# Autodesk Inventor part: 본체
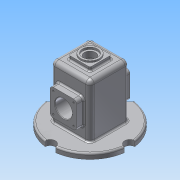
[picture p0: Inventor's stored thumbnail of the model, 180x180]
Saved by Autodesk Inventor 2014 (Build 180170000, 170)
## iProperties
Created: 2018-07
Part Number: 본체
Material: 알루미늄 6061
Document SubType Name: Modeling
Designer: user
Density: 2.71 g/cm^3
Appearance: 알루미늄 - 평지
Mass: 924.652 g
Surface Area: 1023.59 cm^2
Volume: 341.2 cm^3
Author: user
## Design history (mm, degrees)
sketch "스케치1"
  geometry: A1 r 10 centre (0, 75) between (9.978, 74.333) and (-9.978, 74.333); A2 r 10 centre (75, 0) between (74.333, -9.978) and (74.333, 9.978); A3 r 10 centre (0, -75) between (-9.978, -74.333) and (9.978, -74.333); A4 r 10 centre (-75, 0) between (-74.333, 9.978) and (-74.333, -9.978); A5 r 75 centre (0, 0) between (74.333, 9.978) and (9.978, 74.333); A6 r 75 centre (0, 0) between (9.978, -74.333) and (74.333, -9.978); A7 r 75 centre (0, 0) between (-9.978, 74.333) and (-74.333, 9.978); A8 r 75 centre (0, 0) between (-74.333, -9.978) and (-9.978, -74.333); 1 further point
  constraints: 16 point on circle, 8 centre point, 3 equal radius, 2 horizontal alignment, 2 vertical alignment, 1 coincident
  dimensions: "d5" = 75 radius of A5; "d6" = 75 radius of A6; "d7" = 75 radius of A8; "d8" = 75 radius of A7; "d9" = 150 distance of A4.centre A2.centre; "d10" = 150 distance of A3.centre A1.centre; "d11" = 75 distance of A1.centre point (0, 0); "d12" = 75 distance of point (0, 0) A2.centre; "d90" = 20 diameter of A3
extrude "돌출1" new body sketch "스케치1" distance "d13" = 10; taper "d14" = 0 deg
sketch "스케치2"
  geometry: L1 (-37, 37)-(37, 37); L2 (37, 37)-(37, -37); L3 (37, -37)-(-37, -37); L4 (-37, -37)-(-37, 37); L5 (-37, 37)-(37, -37); L6 (37, 37)-(-37, -37); A1 r 75 centre (0, 0) between (74.333, 9.978) and (9.978, 74.333) reference
  constraints: 12 end point, 2 midpoint, 2 parallel, 1 horizontal, 1 perpendicular
  dimensions: "d15" = 74 distance of L2.end L3.end; "d16" = 74 distance of L1.end L2.end
extrude "돌출2" join sketch "스케치2" distance "d17" = 100; taper "d18" = 0 deg
sketch "스케치3"
  geometry: L1 (-20, 20)-(20, 20); L2 (20, 20)-(20, -20); L3 (20, -20)-(-20, -20); L4 (-20, -20)-(-20, 20); L5 (-20, 20)-(20, -20); L6 (20, 20)-(-20, -20); 1 further point
  constraints: 12 end point, 2 midpoint, 2 parallel, 1 horizontal, 1 perpendicular
  dimensions: "d19" = 40 distance of L2.end L3.end; "d20" = 40 distance of L1.end L2.end
extrude "돌출3" join sketch "스케치3" distance "d21" = 7; taper "d22" = 0 deg
sketch "스케치4"
  geometry: C1 r 17.5 at (0, 0); 1 further point
  constraints: 1 centre point, 1 coincident
  dimensions: "d23" = 35 diameter of C1
extrude "돌출4" join sketch "스케치4" distance "d24" = 3; taper "d25" = 0 deg
sketch "스케치5"
  geometry: L1 (12, 70)-(62, 70); L2 (62, 70)-(62, 20); L3 (62, 20)-(12, 20); L4 (12, 20)-(12, 70); L5 (12, 70)-(62, 20); L6 (62, 70)-(12, 20); L7 (111.333, -10)-(46.978, -10) reference; 3 further points
  constraints: 12 end point, 3 midpoint, 2 parallel, 1 horizontal, 1 perpendicular, 1 vertical alignment
  dimensions: "d26" = 50 distance of L2.end L3.end; "d27" = 50 distance of L1.end L2.end; "d28" = 55 distance from line of point (37, 45) L7
extrude "돌출5" join sketch "스케치5" distance "d29" = 13; taper "d30" = 0 deg
sketch "스케치7"
  geometry: L1 (-32, 32)-(32, 32); L2 (32, 32)-(32, -32); L3 (32, -32)-(-32, -32); L4 (-32, -32)-(-32, 32); L5 (-32, 32)-(32, -32); L6 (32, 32)-(-32, -32); A1 r 75 centre (0, 0) between (74.333, 9.978) and (9.978, 74.333) reference
  constraints: 12 end point, 2 midpoint, 2 parallel, 1 horizontal, 1 perpendicular
  dimensions: "d38" = 64 distance of L2.end L3.end; "d39" = 64 distance of L1.end L2.end
extrude "돌출6" cut sketch "스케치7" distance "d40" = 105; taper "d41" = 0 deg
sketch "스케치9"
  geometry: L1 (64, 0)-(0, 0) reference; L2 (64, 105)-(0, 105) reference; C1 r 25 at (32, 55); 2 further points
  constraints: 1 centre point, 1 midpoint, 1 vertical alignment
  dimensions: "d45" = 50 diameter of C1; "d46" = 55 distance from line of C1.centre L1
extrude "돌출8" join sketch "스케치9" distance "d47" = 7; taper "d48" = -20 deg
sketch "스케치10"
  geometry: L1 (0, 50)-(50, 50) reference; L2 (0, 0)-(0, 50) reference; 4 further points
  constraints: 2 midpoint, 1 horizontal alignment, 1 vertical alignment
hole "구멍2" sketch "스케치10" at (25, 25) diameter "d49" = 32; stored, may be unused: countersink angle "d53" = 90 deg, drill point angle "d55" = 118 deg; dims "d50" = 6, "d51" = 4, "d52" = 2, "d54" = 8
sketch "스케치11"
  geometry: L1 (74, 0)-(74, -100) reference; L2 (19.5, -110)-(54.5, -110) reference; 2 further points
  constraints: 1 other
  dimensions: "d56" = 30 distance from line of point (37, -80) L2; "d57" = 37 distance from line of point (37, -80) L1
feature "엠보싱1" sketch "스케치11" dims "d5" = 75, "d6" = 75, "d7" = 75, "d8" = 75, "d9" = 150, "d10" = 150, "d11" = 75, "d12" = 75, "d58" = 0.5, "d59" = 0, "d90" = 20
hole "구멍3" diameter "d62" = 21; stored, may be unused: countersink angle "d66" = 90 deg, drill point angle "d68" = 118 deg; dims "d60" = 10, "d61" = 10, "d63" = 6, "d64" = 28, "d65" = 4, "d67" = 8
fillet "모깎기1" dims "d69" = 6
sketch "스케치12"
  geometry: A1 r 6 centre (38, -6) between (44, -6) and (38, 0) reference; A2 r 6 centre (0, -6) between (0, 0) and (-6, -6) reference; A3 r 6 centre (0, -44) between (-6, -44) and (0, -50) reference; A4 r 6 centre (38, -44) between (38, -50) and (44, -44) reference; 5 further points
  constraints: 4 coincident
hole "구멍4" sketch "스케치12" at (38, -44), (0, -44), (0, -6), (38, -6) diameter "d70" = 3.242; stored, may be unused: countersink angle "d74" = 90 deg, drill point angle "d76" = 118 deg; dims "d71" = 8, "d72" = 28, "d73" = 4, "d75" = 10
fillet "모깎기2" dims "d77" = 6
fillet "모깎기3" dims "d78" = 8
fillet "모깎기4" dims "d79" = 3
fillet "모깎기5" dims "d80" = 8
fillet "모깎기6" dims "d81" = 3
fillet "모깎기7" dims "d82" = 3
fillet "모깎기8" dims "d83" = 3
fillet "모깎기9" dims "d84" = 3
fillet "모깎기10" dims "d85" = 3
chamfer "모따기1" distance "d86" = 1; stored, may be unused: second distance "d87" = 2, angle "d88" = 45 deg
fillet "모깎기11" dims "d89" = 3
node "솔리드1"
mirror "대칭1"
mirror "대칭2"
mirror "대칭3"
